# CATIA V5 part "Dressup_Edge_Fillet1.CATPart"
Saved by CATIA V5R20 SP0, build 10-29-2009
Part number: Part1
Bounding box of the stored display mesh (mm): x -150.129 to 32.969, y -186.929 to 99.8, z 0 to 30
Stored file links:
  G:\카티아자료\수업자료\툴바예제\2 PartDesign\Dressup_Edge_Fillet1.CATPart
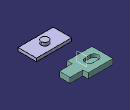
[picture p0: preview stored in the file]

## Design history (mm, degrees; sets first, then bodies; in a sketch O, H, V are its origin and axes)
Set1
  Plane1: type Offset, RefPlane yz-plane, Offset -98
Body1 (main body)
  Sketch1 on xy-plane, origin (0, 0, 0), H (1, 0, 0), V (0, 1, 0)
    point P1 (-150.1294, 99.8002)
    line L1 (-150.1294, 99.8002) -> (-29.8742, 99.8002)
    line L2 (-29.8742, -2.1998) -> (-150.1294, -2.1998)
    point P5 (-150.1294, 99.8002)
    line L3 (-150.1294, -2.1998) -> (-150.1294, 99.8002)
    line L4 (-29.8742, 99.8002) -> (-29.8742, 74.8002)
    line L5 (-29.8742, 74.8002) -> (32.969, 74.8002)
    line L6 (32.969, 74.8002) -> (32.969, 22.8002)
    line L7 (32.969, 22.8002) -> (-29.8742, 22.8002)
    point P9 (-29.8742, 22.8002)
    line L8 (-29.8742, 22.8002) -> (-29.8742, -2.1998)
    horizontal: L1 H, L2 H, L5 H, L7 H
    coincidence: P5 L1, P1 P5, P9 L4
    vertical: L3 V, L4 V, L8 V
    parallelism: L6 L4
  Pad1: profile Sketch1, direction (0, 0, 1), length 25
  Sketch2 on face of Pad1, origin (0, 0, 25), H (1, 0, 0), V (0, 1, 0)
    construction line L1 (-110.7536, 48.8002) -> (-85.7536, 48.8002)
    line L2 (-110.7536, 68.8002) -> (-85.7536, 68.8002)
    line L3 (-85.7536, 28.8002) -> (-110.7536, 28.8002)
    arc A1 centre (-85.7536, 48.8002) radius 20 from (-85.7536, 68.8002) to (-85.7536, 28.8002) cw
    arc A2 centre (-110.7536, 48.8002) radius 20 from (-110.7536, 28.8002) to (-110.7536, 68.8002) cw
    reference projected line E3 (10.1658, 22.8002) -> (-30.1442, 22.8002) from edge [face of Pad1 | face of Pad1]
    reference projected line E4 (-30.1442, 74.8002) -> (10.1658, 74.8002) from edge [face of Pad1 | face of Pad1]
    distance L3 L2 = 40
    length L1 = 25
    horizontal: L1 H
    tangency: A1 L2, A2 L2, A1 L3, A2 L3
    parallelism: L1 L2
    symmetry: E3 E4 L1
  Pocket1: profile Sketch2, direction (0, 0, -1), length 15
Body2
  Sketch3 on start face of Pad1, origin (0, 0, 0), H (1, 0, 0), V (0, -1, 0)
    line L1 (-147.0994, 186.9294) -> (24.0659, 186.9294)
    line L2 (24.0659, 186.9294) -> (24.0659, 97.5271)
    line L3 (24.0659, 97.5271) -> (-147.0994, 97.5271)
    line L4 (-147.0994, 97.5271) -> (-147.0994, 186.9294)
    horizontal: L1 H, L3 H
    vertical: L2 V, L4 V
  Pad2: profile Sketch3, direction (0, 0, 1), length 15
  Sketch4 on end face of Pad2, origin (0, 0, 15), H (1, 0, 0), V (0, 1, 0)
    circle A1 centre (-59.6772, -140.7079) radius 18.0127
  Pad3: profile Sketch4, direction (0, 0, 1), length 15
